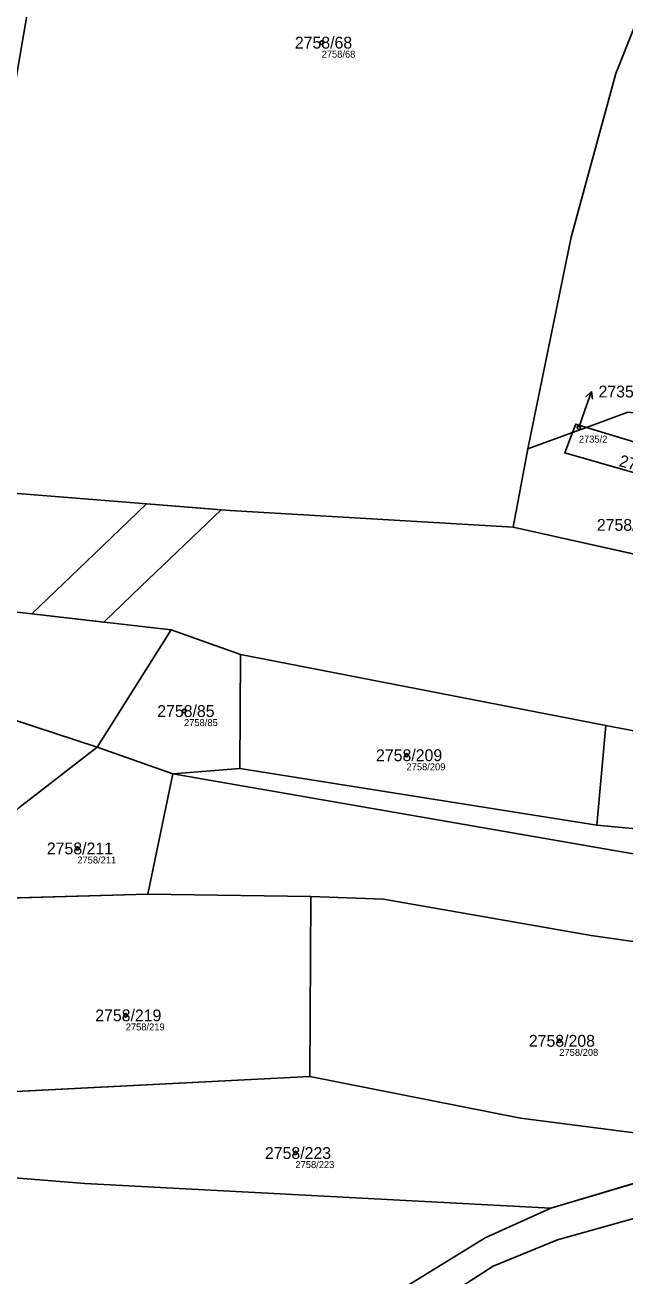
# Model space of a CAD drawing. Extents: x -739214 to -733252, y -1147612 to -1142842.
# Drawn here: x -737943.5 to -737857.5, y -1144474 to -1144294.5 of the extents above; entities that cross this region are included whole.
import ezdxf

# ---------------------------------------------------------------- set-up
doc = ezdxf.new("R2010")
doc.units = 0
for name, color, linetype in [('Definiční body', 7, 'Continuous'), ('Hranice parcel', 7, 'Continuous'), ('Parcelní čísla', 7, 'Continuous'), ('Polygon parcely', 7, 'Continuous'), ('Pop  PČ popisy', 7, 'Continuous'), ('Věcná břemena k části', 7, 'Continuous')]:
    doc.layers.add(name, color=color, linetype=linetype)

msp = doc.modelspace()

# ---------------------------------------------------------------- linework, layer by layer
at = {"layer": 'Definiční body'}
for centre in [(-737901.01, -1144297.06), (-737864.13, -1144352.29), (-737920.74, -1144392.96), (-737888.84, -1144399.3), (-737936.04, -1144412.67), (-737929.1, -1144436.62), (-737866.93, -1144440.27), (-737904.77, -1144456.37)]:
    msp.add_circle(centre, 0.25, dxfattribs=at)
at = {"layer": 'Hranice parcel'}
for p, q in [((-737865.02, -1144352.99), (-737871.43, -1144355.33)), ((-737863.03, -1144352.26), (-737865.02, -1144352.99)), ((-737839.66, -1144359.37), (-737863.03, -1144352.26)), ((-737873.57, -1144366.58), (-737871.43, -1144355.33)), ((-737873.57, -1144366.58), (-737839.61, -1144374.13)), ((-737922.57, -1144381.31), (-737933.2, -1144398.14)), ((-737912.63, -1144384.83), (-737922.57, -1144381.31)), ((-737912.72, -1144401.21), (-737912.63, -1144384.83)), ((-737912.63, -1144384.83), (-737860.24, -1144395.01)), ((-737861.54, -1144409.35), (-737860.24, -1144395.01)), ((-737860.24, -1144395.01), (-737855.23, -1144395.98)), ((-737933.2, -1144398.14), (-737922.34, -1144401.98)), ((-737925.92, -1144419.24), (-737922.34, -1144401.98)), ((-737922.34, -1144401.98), (-737912.72, -1144401.21)), ((-737912.72, -1144401.21), (-737861.54, -1144409.35)), ((-737958.2, -1144420.16), (-737925.92, -1144419.24)), ((-737925.92, -1144419.24), (-737902.55, -1144419.58)), ((-737902.55, -1144419.58), (-737902.69, -1144445.41)), ((-737955.28, -1144448.06), (-737902.69, -1144445.41)), ((-737835.54, -1144454.6), (-737868.17, -1144464.26))]:
    msp.add_line(p, q, dxfattribs=at)
for points in [[(-737952.35, -1144361.12), (-737944.95, -1144302.96), (-737940.49, -1144276.94), (-737933.97, -1144244.83), (-737924.47, -1144213.16)], [(-737871.43, -1144355.33), (-737865.25, -1144324.99), (-737858.85, -1144301.49), (-737853.3, -1144287.51), (-737842.97, -1144265.49)], [(-738738.82, -1144302.23), (-738653.84, -1144305.16), (-738586.54, -1144309.47), (-738566.57, -1144311.53), (-738524.78, -1144317.73), (-738484.2, -1144325.47), (-738327.99, -1144359.59), (-738267.04, -1144371.3), (-738214.93, -1144377.81), (-738095.97, -1144389), (-738073.34, -1144386.23), (-738041.83, -1144388.81), (-738004.8, -1144395.36), (-737972.87, -1144385.13), (-737933.2, -1144398.14)], [(-737922.57, -1144381.31), (-737966.75, -1144376.24), (-737996.88, -1144379.17), (-738043.03, -1144374), (-738072.48, -1144373.31), (-738084.6, -1144374.06), (-738180.34, -1144367.17), (-738223.15, -1144363.36), (-738262.24, -1144358.54), (-738332.46, -1144344.67)], [(-737839.69, -1144352.09), (-737857.1, -1144350.1), (-737863.03, -1144352.26)], [(-737863.03, -1144352.26), (-737864.56, -1144351.8), (-737865.02, -1144352.99)], [(-737865.02, -1144352.99), (-737866.16, -1144355.92), (-737839.65, -1144363.51)], [(-737952.35, -1144361.12), (-737914.15, -1144364.19), (-737873.57, -1144366.58)], [(-737933.2, -1144398.14), (-737944.43, -1144406.85), (-737958.2, -1144420.16)], [(-737861.54, -1144409.35), (-737832.48, -1144412.05), (-737828.63, -1144400.28)], [(-737922.34, -1144401.98), (-737848.89, -1144414.72), (-737828.71, -1144415.54)], [(-737782.1, -1144434.06), (-737827.86, -1144429.94), (-737841.91, -1144428.1), (-737862.38, -1144425.14), (-737892.14, -1144419.93), (-737902.55, -1144419.58)], [(-737902.69, -1144445.41), (-737872.51, -1144451.39), (-737845.4, -1144454.84)], [(-737926.39, -1144533.41), (-737927.01, -1144530.86), (-737925.24, -1144519.57), (-737921.26, -1144511.11), (-737911.32, -1144499.46), (-737900.13, -1144489.08), (-737888.65, -1144480.5), (-737876.41, -1144472.62), (-737867.2, -1144468.83), (-737814.62, -1144454.1)], [(-737868.17, -1144464.26), (-737934.96, -1144460.74), (-737955.11, -1144459.11)], [(-737868.17, -1144464.26), (-737877.57, -1144468.52), (-737891.83, -1144477.32), (-737904.38, -1144486.62), (-737914.24, -1144496.47), (-737925.02, -1144509.31), (-737929.6, -1144518.25), (-737930.48, -1144525.51)]]:
    msp.add_lwpolyline(points, dxfattribs=at)
at = {"layer": 'Polygon parcely'}
for points in [[(-737940.49, -1144276.94), (-737933.97, -1144244.83), (-737924.47, -1144213.16), (-737940.37, -1144207.23), (-737960.13, -1144201.71), (-737971.87, -1144234.59), (-737975.03, -1144244.24), (-737979.79, -1144263.52), (-737987.22, -1144310.18), (-737989.33, -1144324.26), (-737995.98, -1144360.84), (-737975.49, -1144361.66), (-737952.35, -1144361.12), (-737944.95, -1144302.96)], [(-737858.85, -1144301.49), (-737853.3, -1144287.51), (-737842.97, -1144265.49), (-737868.38, -1144246.05), (-737886.17, -1144233), (-737904.16, -1144222.53), (-737922.96, -1144213.72), (-737924.47, -1144213.16), (-737933.97, -1144244.83), (-737940.49, -1144276.94), (-737944.95, -1144302.96), (-737952.35, -1144361.12), (-737914.15, -1144364.19), (-737873.57, -1144366.58), (-737871.43, -1144355.33), (-737865.25, -1144324.99)], [(-737815.04, -1144283.81), (-737841.56, -1144266.57), (-737842.97, -1144265.49), (-737853.3, -1144287.51), (-737858.85, -1144301.49), (-737865.25, -1144324.99), (-737871.43, -1144355.33), (-737865.02, -1144352.99), (-737864.56, -1144351.8), (-737863.03, -1144352.26), (-737857.1, -1144350.1), (-737839.69, -1144352.09), (-737838.79, -1144344.3), (-737836.22, -1144334.8), (-737826.96, -1144307.78)], [(-737839.69, -1144352.09), (-737857.1, -1144350.1), (-737863.03, -1144352.26), (-737839.66, -1144359.37)], [(-737865.02, -1144352.99), (-737863.03, -1144352.26), (-737864.56, -1144351.8)], [(-737839.65, -1144363.51), (-737866.16, -1144355.92), (-737865.02, -1144352.99), (-737871.43, -1144355.33), (-737873.57, -1144366.58), (-737839.61, -1144374.13)], [(-737839.65, -1144363.51), (-737839.66, -1144359.37), (-737863.03, -1144352.26), (-737865.02, -1144352.99), (-737866.16, -1144355.92)], [(-737922.57, -1144381.31), (-737933.2, -1144398.14), (-737922.34, -1144401.98), (-737912.72, -1144401.21), (-737912.63, -1144384.83)], [(-737861.54, -1144409.35), (-737860.24, -1144395.01), (-737912.63, -1144384.83), (-737912.72, -1144401.21)], [(-737832.48, -1144412.05), (-737828.63, -1144400.28), (-737855.23, -1144395.98), (-737860.24, -1144395.01), (-737861.54, -1144409.35)], [(-737958.2, -1144420.16), (-737925.92, -1144419.24), (-737922.34, -1144401.98), (-737933.2, -1144398.14), (-737944.43, -1144406.85)], [(-737828.71, -1144415.54), (-737823.9, -1144400.88), (-737828.63, -1144400.28), (-737832.48, -1144412.05), (-737861.54, -1144409.35), (-737912.72, -1144401.21), (-737922.34, -1144401.98), (-737848.89, -1144414.72)], [(-737902.55, -1144419.58), (-737892.14, -1144419.93), (-737862.38, -1144425.14), (-737841.91, -1144428.1), (-737827.86, -1144429.94), (-737782.1, -1144434.06), (-737785.47, -1144419.68), (-737828.71, -1144415.54), (-737848.89, -1144414.72), (-737922.34, -1144401.98), (-737925.92, -1144419.24)], [(-737902.69, -1144445.41), (-737902.55, -1144419.58), (-737925.92, -1144419.24), (-737958.2, -1144420.16), (-737955.28, -1144448.06)], [(-737872.51, -1144451.39), (-737845.4, -1144454.84), (-737841.25, -1144447.8), (-737826.82, -1144436.68), (-737807.47, -1144438.93), (-737805.91, -1144445.83), (-737778.65, -1144437.77), (-737774.65, -1144436.65), (-737774.89, -1144434.96), (-737782.1, -1144434.06), (-737827.86, -1144429.94), (-737841.91, -1144428.1), (-737862.38, -1144425.14), (-737892.14, -1144419.93), (-737902.55, -1144419.58), (-737902.69, -1144445.41)], [(-737955.11, -1144459.11), (-737934.96, -1144460.74), (-737868.17, -1144464.26), (-737835.54, -1144454.6), (-737845.4, -1144454.84), (-737872.51, -1144451.39), (-737902.69, -1144445.41), (-737955.28, -1144448.06)], [(-737931.41, -1144530.71), (-737930.97, -1144533.06), (-737926.39, -1144533.41), (-737927.01, -1144530.86), (-737925.24, -1144519.57), (-737921.26, -1144511.11), (-737911.32, -1144499.46), (-737900.13, -1144489.08), (-737888.65, -1144480.5), (-737876.41, -1144472.62), (-737867.2, -1144468.83), (-737814.62, -1144454.1), (-737835.54, -1144454.6), (-737868.17, -1144464.26), (-737877.57, -1144468.52), (-737891.83, -1144477.32), (-737904.38, -1144486.62), (-737914.24, -1144496.47), (-737925.02, -1144509.31), (-737929.6, -1144518.25), (-737930.48, -1144525.51)], [(-737955.11, -1144459.11), (-737955.01, -1144470.75), (-737954.9, -1144484.25), (-737955.35, -1144491.07), (-737956.06, -1144501.75), (-737958.01, -1144530.96), (-737942.95, -1144532.13), (-737930.48, -1144525.51), (-737929.6, -1144518.25), (-737925.02, -1144509.31), (-737914.24, -1144496.47), (-737904.38, -1144486.62), (-737891.83, -1144477.32), (-737877.57, -1144468.52), (-737868.17, -1144464.26), (-737934.96, -1144460.74)]]:
    msp.add_lwpolyline(points, close=True, dxfattribs=at)
for points in [[(-737966.75, -1144376.24), (-737922.57, -1144381.31), (-737912.63, -1144384.83), (-737860.24, -1144395.01), (-737855.23, -1144395.98), (-737842.4, -1144381.17), (-737839.61, -1144374.13), (-737873.57, -1144366.58), (-737914.15, -1144364.19), (-737952.35, -1144361.12)], [(-738214.93, -1144377.81), (-738095.97, -1144389), (-738073.34, -1144386.23), (-738041.83, -1144388.81), (-738004.8, -1144395.36), (-737972.87, -1144385.13), (-737933.2, -1144398.14), (-737922.57, -1144381.31), (-737966.75, -1144376.24), (-737996.88, -1144379.17), (-738043.03, -1144374), (-738072.48, -1144373.31), (-738084.6, -1144374.06), (-738180.34, -1144367.17)], [(-738214.14, -1144433.54), (-738072.79, -1144444.03), (-738041.66, -1144444.11), (-738012.07, -1144444.82), (-738000.68, -1144445.1), (-737991.75, -1144445.32), (-737969.8, -1144446.84), (-737958.42, -1144448.22), (-737955.28, -1144448.06), (-737958.2, -1144420.16), (-737944.43, -1144406.85), (-737933.2, -1144398.14), (-737972.87, -1144385.13), (-738004.8, -1144395.36), (-738041.83, -1144388.81), (-738073.34, -1144386.23), (-738095.97, -1144389), (-738214.93, -1144377.81)], [(-737785.6, -1144478.09), (-737773.14, -1144456.81), (-737776.7, -1144456.47), (-737804.09, -1144453.85), (-737814.62, -1144454.1), (-737867.2, -1144468.83), (-737876.41, -1144472.62), (-737888.65, -1144480.5)]]:
    msp.add_lwpolyline(points, dxfattribs=at)
at = {"layer": 'Pop  PČ popisy'}
for p, q in [((-737863.31, -1144349.95), (-737862.33, -1144347.11)), ((-737862.33, -1144347.11), (-737863.13, -1144347.9)), ((-737862.33, -1144347.11), (-737862.19, -1144348.22)), ((-737864.13, -1144352.29), (-737863.31, -1144349.95))]:
    msp.add_line(p, q, dxfattribs=at)
at = {"layer": 'Věcná břemena k části'}
msp.add_lwpolyline([(-737926.91, -1144375.08), (-737915.42, -1144364.09), (-737926.1, -1144363.23), (-737932.45, -1144369.3), (-737942.58, -1144379.01), (-737932.25, -1144380.2)], close=True, dxfattribs=at)

# ---------------------------------------------------------------- texts
at = {"layer": 'Definiční body'}
for s, p in [('2758/68', (-737901.01, -1144299.22)), ('2735/2', (-737864.13, -1144354.45)), ('2758/85', (-737920.74, -1144395.12)), ('2758/209', (-737888.84, -1144401.46)), ('2758/211', (-737936.04, -1144414.83)), ('2758/219', (-737929.1, -1144438.78)), ('2758/208', (-737866.93, -1144442.43)), ('2758/223', (-737904.77, -1144458.53))]:
    msp.add_text(s, height=1, dxfattribs=at).set_placement(p)
at = {"layer": 'Parcelní čísla'}
for s, p in [('2758/68', (-737904.85, -1144297.91)), ('2735/2', (-737861.31, -1144347.97)), ('2758/169', (-737861.55, -1144367.1)), ('2758/85', (-737924.58, -1144393.81)), ('2758/209', (-737893.21, -1144400.15)), ('2758/211', (-737940.41, -1144413.52)), ('2758/219', (-737933.47, -1144437.47)), ('2758/208', (-737871.3, -1144441.12)), ('2758/223', (-737909.14, -1144457.22))]:
    msp.add_text(s, height=1.7, dxfattribs=at).set_placement(p)
msp.add_text('2735/1', height=1.7, rotation=345, dxfattribs=at).set_placement((-737858.48, -1144357.8))

doc.saveas('drawing.dxf')
